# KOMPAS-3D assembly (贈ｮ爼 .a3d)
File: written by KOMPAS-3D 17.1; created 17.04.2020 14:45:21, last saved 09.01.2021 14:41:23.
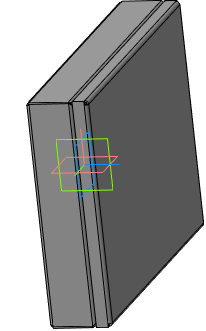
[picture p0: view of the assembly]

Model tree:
1. Сечение:1
2. Сечение:2

Referenced files in E:\laser\Ящик_мойки\: Корпус_ящика.m3d, дверь.m3d
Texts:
  ex71
  длина загиба кромки дверцы
  Толщина листового тела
